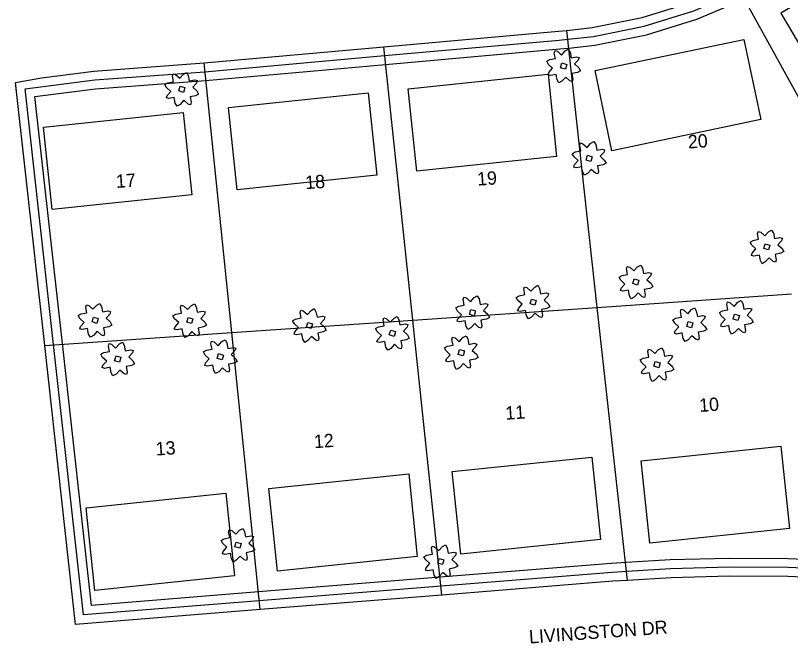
# Model space of a CAD drawing. Extents: x 1810019 to 1811399, y 1074962 to 1076105.
# Drawn here: x 1810125.3 to 1810473.9, y 1075249.2 to 1075531.7 of the extents above; entities that cross this region are included whole.
import ezdxf

# ---------------------------------------------------------------- set-up
doc = ezdxf.new("R2010")
doc.units = 0
for name, color, linetype in [('Environmental-New trees', 7, 'Continuous'), ('Property-Buildings', 7, 'Continuous'), ('Roadway-Land lines', 7, 'Continuous'), ('Roadway-Sidewalks', 7, 'Continuous'), ('Text-Property owner', 7, 'Continuous'), ('Text-Route label', 7, 'Continuous')]:
    doc.layers.add(name, color=color, linetype=linetype)

msp = doc.modelspace()

# ---------------------------------------------------------------- linework, layer by layer
at = {"layer": 'Environmental-New trees'}
for points in [[(1810364.91, 1075505.07), (1810365.22, 1075506.15), (1810366.91, 1075508.02), (1810365.05, 1075509.71), (1810364.27, 1075511.1), (1810365.63, 1075511.85), (1810368.13, 1075512.35), (1810367.66, 1075514.82), (1810367.97, 1075515.9), (1810369.05, 1075515.6), (1810370.91, 1075513.9), (1810372.6, 1075515.76), (1810373.99, 1075516.54), (1810374.77, 1075515.15), (1810375.24, 1075512.68), (1810377.71, 1075513.16), (1810378.8, 1075512.85), (1810378.43, 1075511.69), (1810376.8, 1075509.91), (1810378.66, 1075508.21), (1810379.44, 1075506.82), (1810378.08, 1075506.07), (1810375.58, 1075505.57), (1810376.05, 1075503.1), (1810375.74, 1075502.02), (1810374.66, 1075502.32), (1810372.8, 1075504.02), (1810371.11, 1075502.16), (1810369.72, 1075501.38), (1810368.94, 1075502.77), (1810368.47, 1075505.24), (1810366, 1075504.77)], [(1810371.08, 1075510.35), (1810373.24, 1075509.74), (1810372.63, 1075507.57), (1810370.47, 1075508.18)], [(1810193.16, 1075494.65), (1810193.47, 1075495.73), (1810195.16, 1075497.59), (1810193.3, 1075499.29), (1810192.52, 1075500.68), (1810193.87, 1075501.43), (1810196.38, 1075501.93), (1810195.91, 1075504.4), (1810196.21, 1075505.48), (1810197.3, 1075505.18), (1810199.16, 1075503.48), (1810200.85, 1075505.34), (1810202.24, 1075506.12), (1810203.02, 1075504.73), (1810203.49, 1075502.26), (1810205.96, 1075502.73), (1810207.04, 1075502.43), (1810206.67, 1075501.27), (1810205.04, 1075499.49), (1810206.91, 1075497.79), (1810207.68, 1075496.4), (1810206.33, 1075495.65), (1810203.82, 1075495.15), (1810204.3, 1075492.68), (1810203.99, 1075491.6), (1810202.91, 1075491.9), (1810201.05, 1075493.6), (1810199.35, 1075491.74), (1810197.97, 1075490.96), (1810197.19, 1075492.35), (1810196.72, 1075494.82), (1810194.24, 1075494.35)], [(1810199.32, 1075499.93), (1810201.49, 1075499.32), (1810200.88, 1075497.15), (1810198.71, 1075497.76)], [(1810376.4, 1075463.53), (1810376.71, 1075464.61), (1810378.4, 1075466.47), (1810376.54, 1075468.16), (1810375.76, 1075469.55), (1810377.11, 1075470.31), (1810379.62, 1075470.8), (1810379.15, 1075473.27), (1810379.45, 1075474.36), (1810380.54, 1075474.05), (1810382.4, 1075472.36), (1810384.09, 1075474.22), (1810385.48, 1075475), (1810386.26, 1075473.61), (1810386.73, 1075471.14), (1810389.2, 1075471.61), (1810390.28, 1075471.31), (1810389.91, 1075470.15), (1810388.29, 1075468.36), (1810390.15, 1075466.67), (1810390.92, 1075465.28), (1810389.57, 1075464.52), (1810387.06, 1075464.03), (1810387.54, 1075461.56), (1810387.23, 1075460.48), (1810386.15, 1075460.78), (1810384.29, 1075462.47), (1810382.59, 1075460.61), (1810381.21, 1075459.84), (1810380.43, 1075461.22), (1810379.96, 1075463.69), (1810377.48, 1075463.22)], [(1810382.56, 1075468.81), (1810384.73, 1075468.19), (1810384.12, 1075466.03), (1810381.95, 1075466.64)], [(1810456.34, 1075423.74), (1810456.65, 1075424.82), (1810458.34, 1075426.68), (1810456.48, 1075428.38), (1810455.7, 1075429.77), (1810457.05, 1075430.52), (1810459.56, 1075431.02), (1810459.09, 1075433.49), (1810459.39, 1075434.57), (1810460.48, 1075434.27), (1810462.34, 1075432.57), (1810464.03, 1075434.43), (1810465.42, 1075435.21), (1810466.2, 1075433.82), (1810466.67, 1075431.35), (1810469.14, 1075431.82), (1810470.22, 1075431.52), (1810469.86, 1075430.36), (1810468.23, 1075428.57), (1810470.09, 1075426.88), (1810470.87, 1075425.49), (1810469.51, 1075424.74), (1810467.01, 1075424.24), (1810467.48, 1075421.77), (1810467.17, 1075420.69), (1810466.09, 1075420.99), (1810464.23, 1075422.69), (1810462.54, 1075420.83), (1810461.15, 1075420.05), (1810460.37, 1075421.44), (1810459.9, 1075423.91), (1810457.43, 1075423.43)], [(1810462.51, 1075429.02), (1810464.67, 1075428.41), (1810464.06, 1075426.24), (1810461.9, 1075426.85)], [(1810397.42, 1075407.97), (1810397.73, 1075409.05), (1810399.42, 1075410.91), (1810397.56, 1075412.6), (1810396.78, 1075413.99), (1810398.14, 1075414.75), (1810400.64, 1075415.24), (1810400.17, 1075417.71), (1810400.48, 1075418.8), (1810401.56, 1075418.49), (1810403.42, 1075416.8), (1810405.11, 1075418.66), (1810406.5, 1075419.44), (1810407.28, 1075418.05), (1810407.75, 1075415.58), (1810410.22, 1075416.05), (1810411.31, 1075415.75), (1810410.94, 1075414.59), (1810409.31, 1075412.8), (1810411.17, 1075411.11), (1810411.95, 1075409.72), (1810410.59, 1075408.96), (1810408.09, 1075408.47), (1810408.56, 1075406), (1810408.25, 1075404.92), (1810407.17, 1075405.22), (1810405.31, 1075406.91), (1810403.62, 1075405.05), (1810402.23, 1075404.27), (1810401.45, 1075405.66), (1810400.98, 1075408.13), (1810398.51, 1075407.66)], [(1810403.59, 1075413.24), (1810405.75, 1075412.63), (1810405.14, 1075410.47), (1810402.98, 1075411.08)], [(1810351.17, 1075398.88), (1810351.48, 1075399.96), (1810353.17, 1075401.82), (1810351.31, 1075403.51), (1810350.53, 1075404.9), (1810351.89, 1075405.66), (1810354.39, 1075406.15), (1810353.92, 1075408.62), (1810354.23, 1075409.71), (1810355.31, 1075409.4), (1810357.17, 1075407.71), (1810358.86, 1075409.57), (1810360.25, 1075410.35), (1810361.03, 1075408.96), (1810361.5, 1075406.49), (1810363.97, 1075406.96), (1810365.06, 1075406.65), (1810364.69, 1075405.5), (1810363.06, 1075403.71), (1810364.92, 1075402.02), (1810365.7, 1075400.63), (1810364.35, 1075399.87), (1810361.84, 1075399.38), (1810362.31, 1075396.91), (1810362.01, 1075395.82), (1810360.92, 1075396.13), (1810359.06, 1075397.82), (1810357.37, 1075395.96), (1810355.98, 1075395.18), (1810355.2, 1075396.57), (1810354.73, 1075399.04), (1810352.26, 1075398.57)], [(1810323.95, 1075394.14), (1810324.26, 1075395.22), (1810325.95, 1075397.08), (1810324.09, 1075398.77), (1810323.31, 1075400.16), (1810324.66, 1075400.92), (1810327.17, 1075401.41), (1810326.7, 1075403.88), (1810327, 1075404.97), (1810328.09, 1075404.66), (1810329.95, 1075402.97), (1810331.64, 1075404.83), (1810333.03, 1075405.61), (1810333.81, 1075404.22), (1810334.28, 1075401.75), (1810336.75, 1075402.22), (1810337.83, 1075401.92), (1810337.46, 1075400.76), (1810335.83, 1075398.97), (1810337.7, 1075397.28), (1810338.47, 1075395.89), (1810337.12, 1075395.13), (1810334.61, 1075394.64), (1810335.09, 1075392.17), (1810334.78, 1075391.08), (1810333.7, 1075391.39), (1810331.84, 1075393.08), (1810330.14, 1075391.22), (1810328.76, 1075390.44), (1810327.98, 1075391.83), (1810327.51, 1075394.3), (1810325.03, 1075393.83)], [(1810154.17, 1075390.71), (1810154.47, 1075391.8), (1810156.17, 1075393.66), (1810154.31, 1075395.35), (1810153.53, 1075396.74), (1810154.88, 1075397.5), (1810157.39, 1075397.99), (1810156.92, 1075400.46), (1810157.22, 1075401.54), (1810158.3, 1075401.24), (1810160.16, 1075399.55), (1810161.86, 1075401.41), (1810163.25, 1075402.18), (1810164.02, 1075400.8), (1810164.5, 1075398.33), (1810166.97, 1075398.8), (1810168.05, 1075398.49), (1810167.68, 1075397.34), (1810166.05, 1075395.55), (1810167.91, 1075393.86), (1810168.69, 1075392.47), (1810167.34, 1075391.71), (1810164.83, 1075391.22), (1810165.31, 1075388.74), (1810165, 1075387.66), (1810163.92, 1075387.97), (1810162.06, 1075389.66), (1810160.36, 1075387.8), (1810158.97, 1075387.02), (1810158.2, 1075388.41), (1810157.72, 1075390.88), (1810155.25, 1075390.41)], [(1810196.74, 1075390.59), (1810197.05, 1075391.67), (1810198.74, 1075393.53), (1810196.88, 1075395.23), (1810196.1, 1075396.61), (1810197.45, 1075397.37), (1810199.96, 1075397.87), (1810199.49, 1075400.34), (1810199.79, 1075401.42), (1810200.88, 1075401.11), (1810202.74, 1075399.42), (1810204.43, 1075401.28), (1810205.82, 1075402.06), (1810206.6, 1075400.67), (1810207.07, 1075398.2), (1810209.54, 1075398.67), (1810210.63, 1075398.37), (1810210.26, 1075397.21), (1810208.63, 1075395.42), (1810210.49, 1075393.73), (1810211.27, 1075392.34), (1810209.91, 1075391.58), (1810207.41, 1075391.09), (1810207.88, 1075388.62), (1810207.57, 1075387.54), (1810206.49, 1075387.84), (1810204.63, 1075389.54), (1810202.94, 1075387.67), (1810201.55, 1075386.9), (1810200.77, 1075388.28), (1810200.3, 1075390.76), (1810197.83, 1075390.28)], [(1810357.34, 1075404.15), (1810359.5, 1075403.54), (1810358.89, 1075401.38), (1810356.73, 1075401.99)], [(1810442.55, 1075392.02), (1810442.86, 1075393.1), (1810444.55, 1075394.96), (1810442.69, 1075396.65), (1810441.91, 1075398.04), (1810443.26, 1075398.8), (1810445.77, 1075399.29), (1810445.3, 1075401.76), (1810445.6, 1075402.85), (1810446.68, 1075402.54), (1810448.55, 1075400.85), (1810450.24, 1075402.71), (1810451.63, 1075403.49), (1810452.41, 1075402.1), (1810452.88, 1075399.63), (1810455.35, 1075400.1), (1810456.43, 1075399.8), (1810456.06, 1075398.64), (1810454.43, 1075396.85), (1810456.3, 1075395.16), (1810457.07, 1075393.77), (1810455.72, 1075393.01), (1810453.21, 1075392.52), (1810453.69, 1075390.05), (1810453.38, 1075388.96), (1810452.3, 1075389.27), (1810450.44, 1075390.96), (1810448.74, 1075389.1), (1810447.36, 1075388.32), (1810446.58, 1075389.71), (1810446.1, 1075392.18), (1810443.63, 1075391.71)], [(1810250.59, 1075388.37), (1810250.9, 1075389.45), (1810252.59, 1075391.31), (1810250.73, 1075393), (1810249.95, 1075394.39), (1810251.3, 1075395.15), (1810253.81, 1075395.64), (1810253.34, 1075398.11), (1810253.64, 1075399.2), (1810254.73, 1075398.89), (1810256.59, 1075397.2), (1810258.28, 1075399.06), (1810259.67, 1075399.84), (1810260.45, 1075398.45), (1810260.92, 1075395.98), (1810263.39, 1075396.45), (1810264.47, 1075396.15), (1810264.11, 1075394.99), (1810262.48, 1075393.2), (1810264.34, 1075391.51), (1810265.11, 1075390.12), (1810263.76, 1075389.36), (1810261.25, 1075388.87), (1810261.73, 1075386.4), (1810261.42, 1075385.31), (1810260.34, 1075385.62), (1810258.48, 1075387.31), (1810256.78, 1075385.45), (1810255.4, 1075384.67), (1810254.62, 1075386.06), (1810254.15, 1075388.53), (1810251.67, 1075388.06)], [(1810330.11, 1075399.41), (1810332.28, 1075398.8), (1810331.67, 1075396.64), (1810329.5, 1075397.25)], [(1810421.67, 1075388.73), (1810421.97, 1075389.81), (1810423.67, 1075391.67), (1810421.8, 1075393.36), (1810421.03, 1075394.75), (1810422.38, 1075395.51), (1810424.89, 1075396), (1810424.41, 1075398.47), (1810424.72, 1075399.56), (1810425.8, 1075399.25), (1810427.66, 1075397.56), (1810429.36, 1075399.42), (1810430.74, 1075400.2), (1810431.52, 1075398.81), (1810432, 1075396.34), (1810434.47, 1075396.81), (1810435.55, 1075396.51), (1810435.18, 1075395.35), (1810433.55, 1075393.56), (1810435.41, 1075391.87), (1810436.19, 1075390.48), (1810434.84, 1075389.72), (1810432.33, 1075389.23), (1810432.8, 1075386.76), (1810432.5, 1075385.68), (1810431.42, 1075385.98), (1810429.55, 1075387.67), (1810427.86, 1075385.81), (1810426.47, 1075385.03), (1810425.69, 1075386.42), (1810425.22, 1075388.89), (1810422.75, 1075388.42)], [(1810160.33, 1075395.99), (1810162.5, 1075395.38), (1810161.89, 1075393.21), (1810159.72, 1075393.83)], [(1810202.91, 1075395.87), (1810205.07, 1075395.26), (1810204.46, 1075393.09), (1810202.3, 1075393.7)], [(1810287.9, 1075384.87), (1810288.21, 1075385.95), (1810289.9, 1075387.81), (1810288.04, 1075389.51), (1810287.26, 1075390.9), (1810288.61, 1075391.65), (1810291.12, 1075392.15), (1810290.65, 1075394.62), (1810290.95, 1075395.7), (1810292.03, 1075395.4), (1810293.9, 1075393.7), (1810295.59, 1075395.56), (1810296.98, 1075396.34), (1810297.76, 1075394.95), (1810298.23, 1075392.48), (1810300.7, 1075392.95), (1810301.78, 1075392.65), (1810301.41, 1075391.49), (1810299.78, 1075389.7), (1810301.65, 1075388.01), (1810302.42, 1075386.62), (1810301.07, 1075385.87), (1810298.56, 1075385.37), (1810299.04, 1075382.9), (1810298.73, 1075381.82), (1810297.65, 1075382.12), (1810295.79, 1075383.82), (1810294.09, 1075381.96), (1810292.71, 1075381.18), (1810291.93, 1075382.57), (1810291.45, 1075385.04), (1810288.98, 1075384.56)], [(1810448.71, 1075397.29), (1810450.88, 1075396.68), (1810450.27, 1075394.52), (1810448.1, 1075395.13)], [(1810256.75, 1075393.64), (1810258.92, 1075393.03), (1810258.31, 1075390.87), (1810256.14, 1075391.48)], [(1810427.83, 1075394), (1810430, 1075393.39), (1810429.39, 1075391.23), (1810427.22, 1075391.84)], [(1810294.06, 1075390.15), (1810296.23, 1075389.54), (1810295.62, 1075387.37), (1810293.45, 1075387.98)], [(1810164.36, 1075373.28), (1810164.66, 1075374.36), (1810166.36, 1075376.22), (1810164.5, 1075377.91), (1810163.72, 1075379.3), (1810165.07, 1075380.06), (1810167.58, 1075380.55), (1810167.1, 1075383.02), (1810167.41, 1075384.11), (1810168.49, 1075383.8), (1810170.35, 1075382.11), (1810172.05, 1075383.97), (1810173.44, 1075384.75), (1810174.21, 1075383.36), (1810174.69, 1075380.89), (1810177.16, 1075381.36), (1810178.24, 1075381.05), (1810177.87, 1075379.9), (1810176.24, 1075378.11), (1810178.1, 1075376.42), (1810178.88, 1075375.03), (1810177.53, 1075374.27), (1810175.02, 1075373.78), (1810175.49, 1075371.31), (1810175.19, 1075370.22), (1810174.11, 1075370.53), (1810172.25, 1075372.22), (1810170.55, 1075370.36), (1810169.16, 1075369.58), (1810168.39, 1075370.97), (1810167.91, 1075373.44), (1810165.44, 1075372.97)], [(1810210.49, 1075374.31), (1810210.8, 1075375.39), (1810212.49, 1075377.25), (1810210.63, 1075378.94), (1810209.85, 1075380.33), (1810211.21, 1075381.09), (1810213.71, 1075381.58), (1810213.24, 1075384.05), (1810213.54, 1075385.14), (1810214.63, 1075384.83), (1810216.49, 1075383.14), (1810218.18, 1075385), (1810219.57, 1075385.78), (1810220.35, 1075384.39), (1810220.82, 1075381.92), (1810223.29, 1075382.39), (1810224.38, 1075382.08), (1810224.01, 1075380.93), (1810222.38, 1075379.14), (1810224.24, 1075377.45), (1810225.02, 1075376.06), (1810223.66, 1075375.3), (1810221.16, 1075374.81), (1810221.63, 1075372.34), (1810221.32, 1075371.25), (1810220.24, 1075371.56), (1810218.38, 1075373.25), (1810216.69, 1075371.39), (1810215.3, 1075370.61), (1810214.52, 1075372), (1810214.05, 1075374.47), (1810211.58, 1075374)], [(1810318.88, 1075376.14), (1810319.19, 1075377.22), (1810320.88, 1075379.08), (1810319.02, 1075380.78), (1810318.24, 1075382.17), (1810319.59, 1075382.92), (1810322.1, 1075383.42), (1810321.63, 1075385.89), (1810321.93, 1075386.97), (1810323.02, 1075386.67), (1810324.88, 1075384.97), (1810326.57, 1075386.83), (1810327.96, 1075387.61), (1810328.74, 1075386.22), (1810329.21, 1075383.75), (1810331.68, 1075384.23), (1810332.76, 1075383.92), (1810332.39, 1075382.76), (1810330.76, 1075380.98), (1810332.63, 1075379.28), (1810333.4, 1075377.89), (1810332.05, 1075377.14), (1810329.54, 1075376.64), (1810330.02, 1075374.17), (1810329.71, 1075373.09), (1810328.63, 1075373.39), (1810326.77, 1075375.09), (1810325.07, 1075373.23), (1810323.69, 1075372.45), (1810322.91, 1075373.84), (1810322.44, 1075376.31), (1810319.96, 1075375.84)], [(1810325.04, 1075381.42), (1810327.21, 1075380.81), (1810326.6, 1075378.64), (1810324.43, 1075379.25)], [(1810406.9, 1075370.77), (1810407.2, 1075371.85), (1810408.9, 1075373.71), (1810407.04, 1075375.4), (1810406.26, 1075376.79), (1810407.61, 1075377.55), (1810410.12, 1075378.04), (1810409.65, 1075380.51), (1810409.95, 1075381.6), (1810411.03, 1075381.29), (1810412.89, 1075379.6), (1810414.59, 1075381.46), (1810415.98, 1075382.24), (1810416.75, 1075380.85), (1810417.23, 1075378.38), (1810419.7, 1075378.85), (1810420.78, 1075378.55), (1810420.41, 1075377.39), (1810418.78, 1075375.6), (1810420.64, 1075373.91), (1810421.42, 1075372.52), (1810420.07, 1075371.76), (1810417.56, 1075371.27), (1810418.04, 1075368.8), (1810417.73, 1075367.71), (1810416.65, 1075368.02), (1810414.79, 1075369.71), (1810413.09, 1075367.85), (1810411.7, 1075367.07), (1810410.93, 1075368.46), (1810410.45, 1075370.93), (1810407.98, 1075370.46)], [(1810170.52, 1075378.55), (1810172.69, 1075377.94), (1810172.08, 1075375.78), (1810169.91, 1075376.39)], [(1810216.66, 1075379.58), (1810218.82, 1075378.97), (1810218.21, 1075376.81), (1810216.05, 1075377.42)], [(1810413.06, 1075376.04), (1810415.23, 1075375.43), (1810414.62, 1075373.27), (1810412.45, 1075373.88)], [(1810218.43, 1075289.52), (1810218.73, 1075290.6), (1810220.43, 1075292.46), (1810218.57, 1075294.16), (1810217.79, 1075295.55), (1810219.14, 1075296.3), (1810221.65, 1075296.8), (1810221.17, 1075299.27), (1810221.48, 1075300.35), (1810222.56, 1075300.05), (1810224.42, 1075298.35), (1810226.12, 1075300.21), (1810227.51, 1075300.99), (1810228.28, 1075299.6), (1810228.76, 1075297.13), (1810231.23, 1075297.6), (1810232.31, 1075297.3), (1810231.94, 1075296.14), (1810230.31, 1075294.36), (1810232.17, 1075292.66), (1810232.95, 1075291.27), (1810231.6, 1075290.52), (1810229.09, 1075290.02), (1810229.56, 1075287.55), (1810229.26, 1075286.47), (1810228.18, 1075286.77), (1810226.31, 1075288.47), (1810224.62, 1075286.61), (1810223.23, 1075285.83), (1810222.46, 1075287.22), (1810221.98, 1075289.69), (1810219.51, 1075289.21)], [(1810224.59, 1075294.8), (1810226.76, 1075294.19), (1810226.15, 1075292.02), (1810223.98, 1075292.63)], [(1810309.66, 1075282.16), (1810309.97, 1075283.24), (1810311.66, 1075285.1), (1810309.8, 1075286.8), (1810309.02, 1075288.19), (1810310.37, 1075288.94), (1810312.88, 1075289.44), (1810312.41, 1075291.91), (1810312.71, 1075292.99), (1810313.8, 1075292.69), (1810315.66, 1075290.99), (1810317.35, 1075292.85), (1810318.74, 1075293.63), (1810319.52, 1075292.24), (1810319.99, 1075289.77), (1810322.46, 1075290.24), (1810323.54, 1075289.94), (1810323.18, 1075288.78), (1810321.55, 1075287), (1810323.41, 1075285.3), (1810324.19, 1075283.91), (1810322.83, 1075283.16), (1810320.33, 1075282.66), (1810320.8, 1075280.19), (1810320.49, 1075279.11), (1810319.41, 1075279.41), (1810317.55, 1075281.11), (1810315.86, 1075279.25), (1810314.47, 1075278.47), (1810313.69, 1075279.86), (1810313.22, 1075282.33), (1810310.75, 1075281.86)], [(1810315.83, 1075287.44), (1810317.99, 1075286.83), (1810317.38, 1075284.66), (1810315.22, 1075285.27)]]:
    msp.add_lwpolyline(points, close=True, dxfattribs=at)
at = {"layer": 'Property-Buildings'}
for points in [[(1810469.57, 1075532.8), (1810490.73, 1075496.96), (1810541.25, 1075526.79), (1810520.08, 1075562.63)], [(1810385.97, 1075506.93), (1810452.92, 1075520.99), (1810460.49, 1075484.95), (1810393.54, 1075470.89)], [(1810301.99, 1075498.78), (1810364.82, 1075505.37), (1810368.71, 1075468.24), (1810305.88, 1075461.66)], [(1810221.1, 1075490.38), (1810283.94, 1075496.96), (1810287.83, 1075459.83), (1810224.99, 1075453.25)], [(1810137.9, 1075481.52), (1810200.73, 1075488.11), (1810204.62, 1075450.98), (1810141.79, 1075444.4)], [(1810406.71, 1075331.41), (1810469.55, 1075337.99), (1810473.44, 1075300.87), (1810410.6, 1075294.28)], [(1810321.68, 1075326.5), (1810384.51, 1075333.08), (1810388.41, 1075295.95), (1810325.57, 1075289.37)], [(1810239.31, 1075318.87), (1810302.15, 1075325.46), (1810306.04, 1075288.33), (1810243.2, 1075281.75)], [(1810157.14, 1075310.22), (1810219.97, 1075316.8), (1810223.87, 1075279.68), (1810161.03, 1075273.09)]]:
    msp.add_lwpolyline(points, close=True, dxfattribs=at)
at = {"layer": 'Roadway-Land lines'}
for p, q in [((1810524.22, 1075409.88), (1810449.23, 1075546.24)), ((1810290.96, 1075517.64), (1810369.47, 1075524.64)), ((1810369.47, 1075524.64), (1810373.22, 1075524.98)), ((1810386.99, 1075400.41), (1810373.22, 1075524.98)), ((1810210.12, 1075510.44), (1810290.96, 1075517.64)), ((1810303.95, 1075394.68), (1810290.96, 1075517.64)), ((1810222.62, 1075389.07), (1810210.12, 1075510.44)), ((1810138.43, 1075383.26), (1810125.31, 1075501.53)), ((1810386.99, 1075400.41), (1810474.35, 1075406.44)), ((1810303.95, 1075394.68), (1810386.99, 1075400.41)), ((1810400.57, 1075277.57), (1810386.99, 1075400.41)), ((1810222.64, 1075389.07), (1810303.95, 1075394.68)), ((1810317.03, 1075270.98), (1810303.95, 1075394.68)), ((1810138.43, 1075383.26), (1810222.62, 1075389.07)), ((1810222.62, 1075389.07), (1810222.64, 1075389.07)), ((1810235.3, 1075264.41), (1810222.64, 1075389.07)), ((1810152.35, 1075257.74), (1810138.43, 1075383.26)), ((1810393.93, 1075277.16), (1810317.03, 1075270.98)), ((1810400.57, 1075277.57), (1810393.93, 1075277.16)), ((1810317.03, 1075270.98), (1810235.3, 1075264.41)), ((1810235.3, 1075264.41), (1810152.35, 1075257.74))]:
    msp.add_line(p, q, dxfattribs=at)
for points in [[(1810373.22, 1075524.98), (1810384.67, 1075526.29), (1810407.16, 1075530.76), (1810429.05, 1075537.57), (1810449.23, 1075546.24)], [(1810125.31, 1075501.53), (1810136.99, 1075503.67), (1810160.53, 1075506.72), (1810210.12, 1075510.44)], [(1810490.22, 1075278.58), (1810472.68, 1075279.3), (1810446.41, 1075279.48), (1810420.15, 1075278.77), (1810400.57, 1075277.57)]]:
    msp.add_lwpolyline(points, dxfattribs=at)
at = {"layer": 'Roadway-Sidewalks'}
for p, q in [((1810291.31, 1075513.66), (1810369.82, 1075520.66)), ((1810369.83, 1075520.66), (1810373.58, 1075521)), ((1810370.19, 1075516.67), (1810373.95, 1075517.02)), ((1810210.48, 1075506.45), (1810291.31, 1075513.66)), ((1810291.67, 1075509.67), (1810370.18, 1075516.67)), ((1810210.83, 1075502.47), (1810291.67, 1075509.67)), ((1810142.4, 1075383.7), (1810129.65, 1075498.68)), ((1810146.38, 1075384.14), (1810134.06, 1075495.22)), ((1810155.9, 1075262.04), (1810142.4, 1075383.7)), ((1810159.45, 1075266.34), (1810146.38, 1075384.14)), ((1810393.29, 1075285.14), (1810316.39, 1075278.96)), ((1810400.08, 1075285.55), (1810393.44, 1075285.15)), ((1810393.61, 1075281.15), (1810316.71, 1075274.97)), ((1810400.33, 1075281.56), (1810393.69, 1075281.15)), ((1810316.39, 1075278.96), (1810234.66, 1075272.38)), ((1810316.71, 1075274.97), (1810234.98, 1075268.4)), ((1810234.66, 1075272.38), (1810159.45, 1075266.34)), ((1810234.98, 1075268.4), (1810155.9, 1075262.04))]:
    msp.add_line(p, q, dxfattribs=at)
for points in [[(1810373.68, 1075521.01), (1810385.28, 1075522.34), (1810408.14, 1075526.88), (1810430.44, 1075533.82), (1810450.81, 1075542.57)], [(1810374.13, 1075517.03), (1810385.9, 1075518.38), (1810409.13, 1075523), (1810431.82, 1075530.06), (1810452.39, 1075538.89)], [(1810129.65, 1075498.68), (1810160.94, 1075502.74), (1810210.42, 1075506.45)], [(1810134.06, 1075495.22), (1810161.34, 1075498.76), (1810210.72, 1075502.46)], [(1810490.55, 1075286.58), (1810472.87, 1075287.3), (1810446.33, 1075287.48), (1810419.8, 1075286.76), (1810400.08, 1075285.55)], [(1810490.39, 1075282.58), (1810472.78, 1075283.3), (1810446.37, 1075283.48), (1810419.97, 1075282.76), (1810400.33, 1075281.56)]]:
    msp.add_lwpolyline(points, dxfattribs=at)

# ---------------------------------------------------------------- texts
at = {"layer": 'Text-Property owner'}
for s, p in [('20', (1810427.94, 1075471.86)), ('19', (1810333.14, 1075455.15)), ('17', (1810170.68, 1075454.1)), ('18', (1810255.82, 1075453.57)), ('10', (1810433.01, 1075353.33)), ('11', (1810345.79, 1075349.81)), ('12', (1810259.74, 1075337.03)), ('13', (1810188.57, 1075333.72))]:
    msp.add_text(s, height=6, rotation=3.9478, dxfattribs=at).set_placement(p)
at = {"layer": 'Text-Route label'}
msp.add_text('LIVINGSTON DR', height=6, rotation=4.1717, dxfattribs=at).set_placement((1810356.52, 1075249.13))

doc.saveas('drawing.dxf')
